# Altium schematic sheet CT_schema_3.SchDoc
size 273 x 214 mm
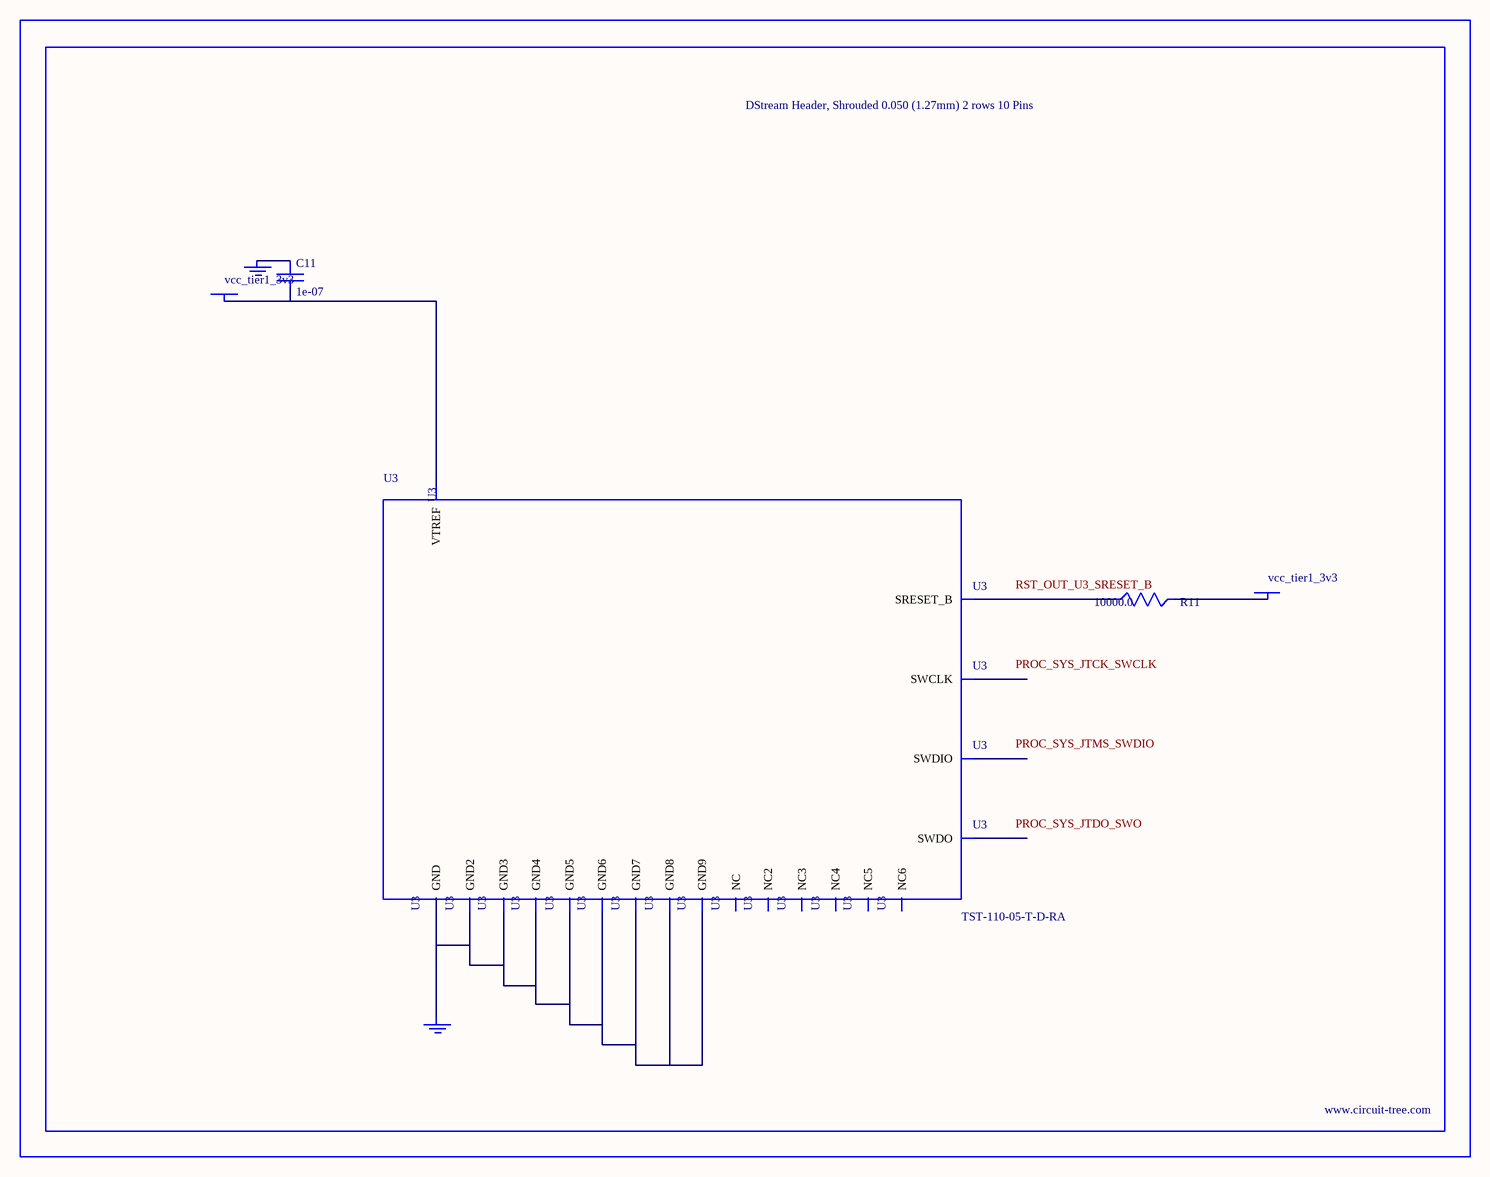
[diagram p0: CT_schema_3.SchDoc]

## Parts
BORDER2  (no value)
C11  1e-07  [C0402]
GND_INSTANCE_2_0  (no value)
GND_INSTANCE_2_1  (no value)
POWER_INSTANCE_2_0  vcc_tier1_3v3
POWER_INSTANCE_2_1  vcc_tier1_3v3
R11  10000.0  [R0603]
U3  TST-110-05-T-D-RA  [TST-110-05-T-D-RA]

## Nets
NetC11_1: C11.1 GND_INSTANCE_2_0.0(GND)
NetC11_2: C11.2 POWER_INSTANCE_2_0.0(PWR) U3.1(VTREF)
NetGND_INSTANCE_2_1_0: GND_INSTANCE_2_1.0(GND) U3.4(GND) U3.6(GND2) U3.8(GND3) U3.10(GND4) U3.12(GND5) U3.14(GND6) U3.16(GND7) U3.18(GND8) U3.20(GND9)
NetPOWER_INSTANCE_2_1_0: POWER_INSTANCE_2_1.0(PWR) R11.2
NetR11_1: R11.1 U3.15(SRESET_B)

Not connected (* = marked no-connect by the designer): U3 2(NC) 3(NC2) 5(NC3) 7(SWDIO) 9(SWCLK) 11(NC4) 13(SWDO) 17(NC5) 19(NC6)

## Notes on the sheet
- Labels drawn without touching a wire or pin: PROC_SYS_JTCK_SWCLK, PROC_SYS_JTDO_SWO, PROC_SYS_JTMS_SWDIO, RST_OUT_U3_SRESET_B

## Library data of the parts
BORDER2 = BORDER_PAGE2
C11 = C0402C104K3RACTU
GND_INSTANCE_2_0 GND_INSTANCE_2_1 = GND
POWER_INSTANCE_2_0 POWER_INSTANCE_2_1 = PWR
R11 = RC0603JR-0710KL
